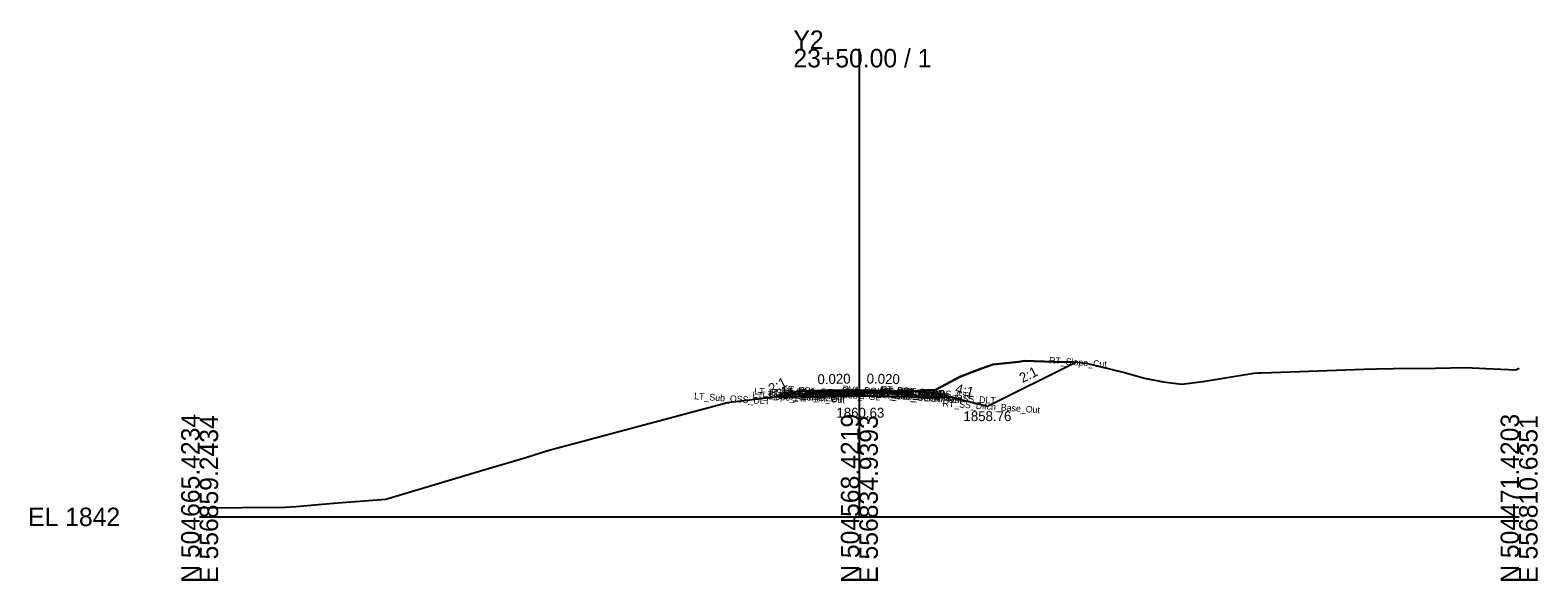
# Model space of a CAD drawing. Extents: x -26 to 1503, y -10 to 3574.
# Drawn here: x -25.7 to 202.8, y 3490.3 to 3573.8 of the extents above; entities that cross this region are included whole.
import ezdxf

# ---------------------------------------------------------------- set-up
doc = ezdxf.new("R2010")
doc.units = 0
for name, color, linetype in [('Default', 7, 'Continuous'), ('Exist Cross Section Cell', 7, 'Continuous'), ('Exist XS Center Line Elevation Label', 7, 'Continuous'), ('Exist XS Ground Line', 7, 'Continuous'), ('Prop CMT Pvmt Course 1', 7, 'Continuous'), ('Prop CMT Pvmt Course 2', 7, 'Continuous'), ('Prop CMT Pvmt Course 3', 7, 'Continuous'), ('Prop CMT Pvmt Surface', 7, 'Continuous'), ('Prop CMT Pvmt Surface Shoulder', 7, 'Continuous'), ('Prop CMT Shld Paved Course 1', 7, 'Continuous'), ('Prop CMT Shld Paved Course 2', 7, 'Continuous'), ('Prop CMT Shld Paved Course 3', 7, 'Continuous'), ('Prop CMT Slope Grass', 7, 'Continuous'), ('Prop CMT Subgrade Earthwork', 7, 'Continuous'), ('Prop XS Ditch Standard Text', 7, 'Continuous'), ('Prop XS Earthwork Shape', 7, 'Continuous'), ('Prop XS SE Text', 7, 'Continuous'), ('Prop XS Side Slope Text', 7, 'Continuous'), ('Typical Text General CELL', 7, 'Continuous')]:
    doc.layers.add(name, color=color, linetype=linetype)

msp = doc.modelspace()

# ---------------------------------------------------------------- linework, layer by layer
at = {"layer": 'Exist Cross Section Cell'}
for p, q in [((100, 3500), (100, 3570.91)), ((0, 3500), (100, 3500)), ((100, 3500), (200, 3500))]:
    msp.add_line(p, q, dxfattribs=at)
at = {"layer": 'Exist XS Ground Line'}
for p, q in [((115.21, 3521.22), (118.51, 3522.47)), ((118.51, 3522.47), (120.23, 3523.11)), ((120.23, 3523.11), (124.19, 3523.49)), ((124.19, 3523.49), (124.96, 3523.64)), ((124.96, 3523.64), (131.08, 3523.43)), ((131.08, 3523.43), (132.72, 3523.47)), ((132.72, 3523.47), (133.44, 3523.4)), ((133.44, 3523.4), (134.38, 3523.29)), ((134.38, 3523.29), (140.2, 3521.89)), ((140.2, 3521.89), (143.2, 3521)), ((152.08, 3520.53), (159.8, 3521.8)), ((159.8, 3521.8), (160.39, 3521.82)), ((160.39, 3521.82), (161.07, 3521.84)), ((161.07, 3521.84), (169.55, 3522.12)), ((169.55, 3522.12), (176.45, 3522.39)), ((176.45, 3522.39), (178.39, 3522.41)), ((178.39, 3522.41), (180.98, 3522.46)), ((180.98, 3522.46), (187.31, 3522.55)), ((187.31, 3522.55), (191.85, 3522.63)), ((191.85, 3522.63), (194.97, 3522.46)), ((194.97, 3522.46), (199.52, 3522.29)), ((199.52, 3522.29), (200, 3522.51)), ((111.55, 3519.27), (113.17, 3520.09)), ((113.17, 3520.09), (115.21, 3521.22)), ((143.2, 3521), (146.07, 3520.44)), ((146.07, 3520.44), (148.87, 3520.09)), ((148.87, 3520.09), (152.08, 3520.53)), ((52.79, 3510.06), (80, 3517.31)), ((80, 3517.31), (80.38, 3517.39)), ((80.38, 3517.39), (88.4, 3518.33)), ((88.4, 3518.33), (89.89, 3518.58)), ((89.89, 3518.58), (91.27, 3518.59)), ((91.27, 3518.59), (99.29, 3518.59)), ((99.29, 3518.59), (100, 3518.63)), ((100, 3518.63), (103.57, 3518.79)), ((103.57, 3518.79), (107.34, 3518.99)), ((107.34, 3518.99), (107.9, 3519.05)), ((107.9, 3519.05), (111.55, 3519.27)), ((42.55, 3506.97), (49.44, 3508.99)), ((49.44, 3508.99), (52.79, 3510.06)), ((28.24, 3502.7), (42.55, 3506.97)), ((0, 3501.36), (12.98, 3501.49)), ((12.98, 3501.49), (14.61, 3501.59)), ((14.61, 3501.59), (20.29, 3502.06)), ((20.29, 3502.06), (28.24, 3502.7))]:
    msp.add_line(p, q, dxfattribs=at)
at = {"layer": 'Prop CMT Pvmt Course 1'}
for points in [[(100, 3519.23), (92.6, 3519.08)], [(92.6, 3519.08), (92.6, 3518.83)], [(92.6, 3518.83), (100, 3518.98)], [(100, 3518.98), (100, 3519.23)], [(100, 3519.23), (107.4, 3519.08)], [(100, 3518.98), (100, 3519.23)], [(107.4, 3518.83), (100, 3518.98)], [(107.4, 3519.08), (107.4, 3518.83)]]:
    msp.add_lwpolyline(points, dxfattribs=at)
at = {"layer": 'Prop CMT Pvmt Course 2'}
for points in [[(100, 3518.98), (92.6, 3518.83)], [(92.6, 3518.83), (92.6, 3518.58)], [(92.6, 3518.58), (100, 3518.73)], [(100, 3518.73), (100, 3518.98)], [(100, 3518.73), (100, 3518.98)], [(100, 3518.98), (107.4, 3518.83)], [(107.4, 3518.58), (100, 3518.73)], [(107.4, 3518.83), (107.4, 3518.58)]]:
    msp.add_lwpolyline(points, dxfattribs=at)
at = {"layer": 'Prop CMT Pvmt Course 3'}
for points in [[(100, 3518.73), (92.6, 3518.58)], [(92.6, 3518.58), (92.6, 3518.21)], [(92.6, 3518.21), (100, 3518.35)], [(100, 3518.35), (100, 3518.73)], [(100, 3518.73), (107.4, 3518.58)], [(100, 3518.35), (100, 3518.73)], [(107.4, 3518.21), (100, 3518.35)], [(107.4, 3518.58), (107.4, 3518.21)]]:
    msp.add_lwpolyline(points, dxfattribs=at)
at = {"layer": 'Prop CMT Pvmt Surface'}
for points in [[(100, 3519.23), (92.6, 3519.08)], [(100, 3519.23), (107.4, 3519.08)]]:
    msp.add_lwpolyline(points, dxfattribs=at)
at = {"layer": 'Prop CMT Pvmt Surface Shoulder'}
for points in [[(92.6, 3519.08), (92.6, 3519.08)], [(107.4, 3519.08), (107.4, 3519.08)]]:
    msp.add_lwpolyline(points, dxfattribs=at)
at = {"layer": 'Prop CMT Shld Paved Course 1'}
for points in [[(92.6, 3519.08), (92.35, 3518.83)], [(92.35, 3518.83), (92.6, 3518.83)], [(92.6, 3519.08), (92.6, 3519.08)], [(92.6, 3518.83), (92.6, 3519.08)], [(107.4, 3519.08), (107.4, 3519.08)], [(107.4, 3519.08), (107.65, 3518.83)], [(107.4, 3518.83), (107.4, 3519.08)], [(107.65, 3518.83), (107.4, 3518.83)]]:
    msp.add_lwpolyline(points, dxfattribs=at)
at = {"layer": 'Prop CMT Shld Paved Course 2'}
for points in [[(92.6, 3518.83), (92.35, 3518.83), (92.09, 3518.57)], [(92.09, 3518.57), (92.6, 3518.58)], [(92.6, 3518.58), (92.6, 3518.83)], [(107.4, 3518.83), (107.65, 3518.83), (107.91, 3518.57)], [(107.4, 3518.58), (107.4, 3518.83)], [(107.91, 3518.57), (107.4, 3518.58)]]:
    msp.add_lwpolyline(points, dxfattribs=at)
at = {"layer": 'Prop CMT Shld Paved Course 3'}
for points in [[(92.6, 3518.58), (92.09, 3518.57), (91.59, 3518.56), (91.21, 3518.18)], [(91.21, 3518.18), (92.6, 3518.21)], [(92.6, 3518.21), (92.6, 3518.58)], [(107.4, 3518.58), (107.91, 3518.57), (108.41, 3518.56), (108.79, 3518.18)], [(107.4, 3518.21), (107.4, 3518.58)], [(108.79, 3518.18), (107.4, 3518.21)]]:
    msp.add_lwpolyline(points, dxfattribs=at)
at = {"layer": 'Prop CMT Slope Grass'}
for points in [[(107.4, 3519.08), (111.4, 3518.76), (119.4, 3516.76), (132.8, 3523.46)], [(92.6, 3519.08), (88.6, 3518.76), (87.54, 3518.23)]]:
    msp.add_lwpolyline(points, dxfattribs=at)
at = {"layer": 'Prop CMT Subgrade Earthwork'}
msp.add_line((91.21, 3518.18), (87.54, 3518.23), dxfattribs=at)
for points in [[(92.6, 3518.21), (91.21, 3518.18)], [(100, 3518.35), (92.6, 3518.21)], [(100, 3518.35), (107.4, 3518.21)], [(107.4, 3518.21), (108.79, 3518.18)], [(108.79, 3518.18), (114.16, 3518.07)]]:
    msp.add_lwpolyline(points, dxfattribs=at)
at = {"layer": 'Prop XS Earthwork Shape'}
for points in [[(107.9, 3519.05), (111.4, 3518.76), (114.16, 3518.07), (119.4, 3516.76), (132.8, 3523.46), (131.08, 3523.43), (124.96, 3523.64), (124.19, 3523.49), (120.23, 3523.11), (118.51, 3522.47), (115.21, 3521.22), (113.17, 3520.09), (111.55, 3519.27)], [(107.4, 3518.21), (108.79, 3518.18), (114.16, 3518.07), (111.4, 3518.76), (107.9, 3519.05), (107.34, 3518.99), (103.57, 3518.79), (100, 3518.63), (99.29, 3518.59), (91.27, 3518.59), (89.89, 3518.58), (88.4, 3518.33), (87.54, 3518.23), (91.21, 3518.18), (92.6, 3518.21), (100, 3518.35)]]:
    msp.add_lwpolyline(points, close=True, dxfattribs=at)

# ---------------------------------------------------------------- texts
at = {"layer": 'Default'}
msp.add_text('-', height=0.0001, dxfattribs=at).set_placement((0, 3500))
at = {"layer": 'Exist Cross Section Cell'}
for s, p in [('Y2', (90, 3570.91)), ('23+50.00 / 1', (90, 3568.11)), ('EL 1842', (-26, 3498.6))]:
    msp.add_text(s, height=2.8, dxfattribs=at).set_placement(p)
for s, p in [('N 504665.4234', (0, 3490)), ('E 556859.2434', (2.8, 3490)), ('N 504568.4219', (100, 3490)), ('E 556834.9393', (102.8, 3490)), ('N 504471.4203', (200, 3490)), ('E 556810.6351', (202.8, 3490))]:
    msp.add_text(s, height=2.8, rotation=90, dxfattribs=at).set_placement(p)
at = {"layer": 'Exist XS Center Line Elevation Label'}
msp.add_text('1860.63', height=1.5, dxfattribs=at).set_placement((96.52, 3515.03))
at = {"layer": 'Prop XS Ditch Standard Text'}
msp.add_text('1858.76', height=1.5, dxfattribs=at).set_placement((115.78, 3514.51))
at = {"layer": 'Prop XS SE Text'}
for rotation, p in [(1.1458, (93.66, 3520.1)), (358.8542, (101.09, 3520.21))]:
    msp.add_text('0.020', height=1.5, rotation=rotation, dxfattribs=at).set_placement(p)
at = {"layer": 'Prop XS Side Slope Text'}
for s, rotation, p in [('2:1', 26.5651, (124.7, 3520.25)), ('2:1', 26.565, (86.67, 3518.63)), ('4:1', 345.9638, (114.43, 3518.78))]:
    msp.add_text(s, height=1.5, rotation=rotation, dxfattribs=at).set_placement(p)
at = {"layer": 'Typical Text General CELL'}
for s, p in [('RT_Slope_Cut', (128.72, 3523.24)), ('LT_GS_OS_CTL', (84.04, 3518.58)), ('LT_PS3_Shelf_Out', (86.23, 3518.43)), ('LT_PS2_OEOP', (88.11, 3518.62)), ('LT_PV2_OEOT', (88.32, 3518.63)), ('LT_PV1_OEOT', (88.44, 3518.87)), ('LT_PS1_OEOP', (88.48, 3518.87)), ('PV2_PGL', (97.32, 3518.66)), ('PV3_PGL', (97.32, 3518.41)), ('PV1_PGL', (97.44, 3518.91)), ('RT_PS3_Shelf_Out', (102.98, 3518.44)), ('RT_PV2_OEOT', (103.06, 3518.63)), ('RT_PV1_OEOT', (103.18, 3518.87)), ('RT_PS1_OEOP', (103.22, 3518.87)), ('RT_PS2_OEOP', (103.36, 3518.62)), ('RT_GS_OS_CTL', (106.78, 3518.58)), ('LT_Sub_OSS_DLT', (74.93, 3517.82)), ('LT_Slope_Fill', (83.75, 3517.99)), ('LT_Sub_Trench_Out', (85.3, 3518.09)), ('LT_PS3_OEOP', (87.85, 3518.37)), ('LT_PV3_OEOT', (88.32, 3518.38)), ('LT_Sub_OEOT', (88.35, 3518)), ('Sub_PGL', (97.35, 3518.04)), ('RT_Sub_Trench_Out', (102.82, 3518.09)), ('RT_PV3_OEOT', (103.06, 3518.38)), ('RT_Sub_OEOT', (103.08, 3518.01)), ('RT_PS3_OEOP', (103.61, 3518.37)), ('RT_Sub_OSS_DLT', (108.92, 3517.93)), ('RT_SS_Ditch_Base_Out', (112.58, 3516.74))]:
    msp.add_text(s, height=1, rotation=356, dxfattribs=at).set_placement(p)

doc.saveas('drawing.dxf')
